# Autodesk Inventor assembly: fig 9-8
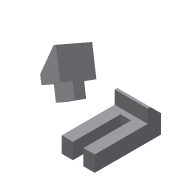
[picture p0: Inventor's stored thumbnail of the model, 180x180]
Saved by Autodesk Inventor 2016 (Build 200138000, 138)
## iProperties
Shininess: 64.0
Length Units: 11269
Angle Units: 11279
Time Units: 11290
Mass Units: 11283
Length Display Precision: 3
Angle Display Precision: 2
Created: 2002-01
Part Number: fig 9-8
Document SubType Name: Assembly
Designer: ***
Density: 0.0
Volumn: 0.0
Area: 0.0
PropertySet Name: Model Information
Control State: 0
Master: False
Checked Out: False
Author: ***
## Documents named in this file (3)
- D:\KAVITA\Autodesk Inventor_ 2016 Project_Kavita\Inventor_Part Files\Inventor_2016_Part\c09_Inv_2016\c09_inv_2016_prt\fig 9-8.iam
- D:\KAVITA\Autodesk Inventor_ 2016 Project_Kavita\Inventor_Part Files\Inventor_2016_Part\c09_Inv_2016\c09_inv_2016_prt\Part3.ipt
- D:\KAVITA\Autodesk Inventor_ 2016 Project_Kavita\Inventor_Part Files\Inventor_2016_Part\c09_Inv_2016\c09_inv_2016_prt\Part4.ipt
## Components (2 placed, 2 different names)
1. Part3:1
2. Part4:1
